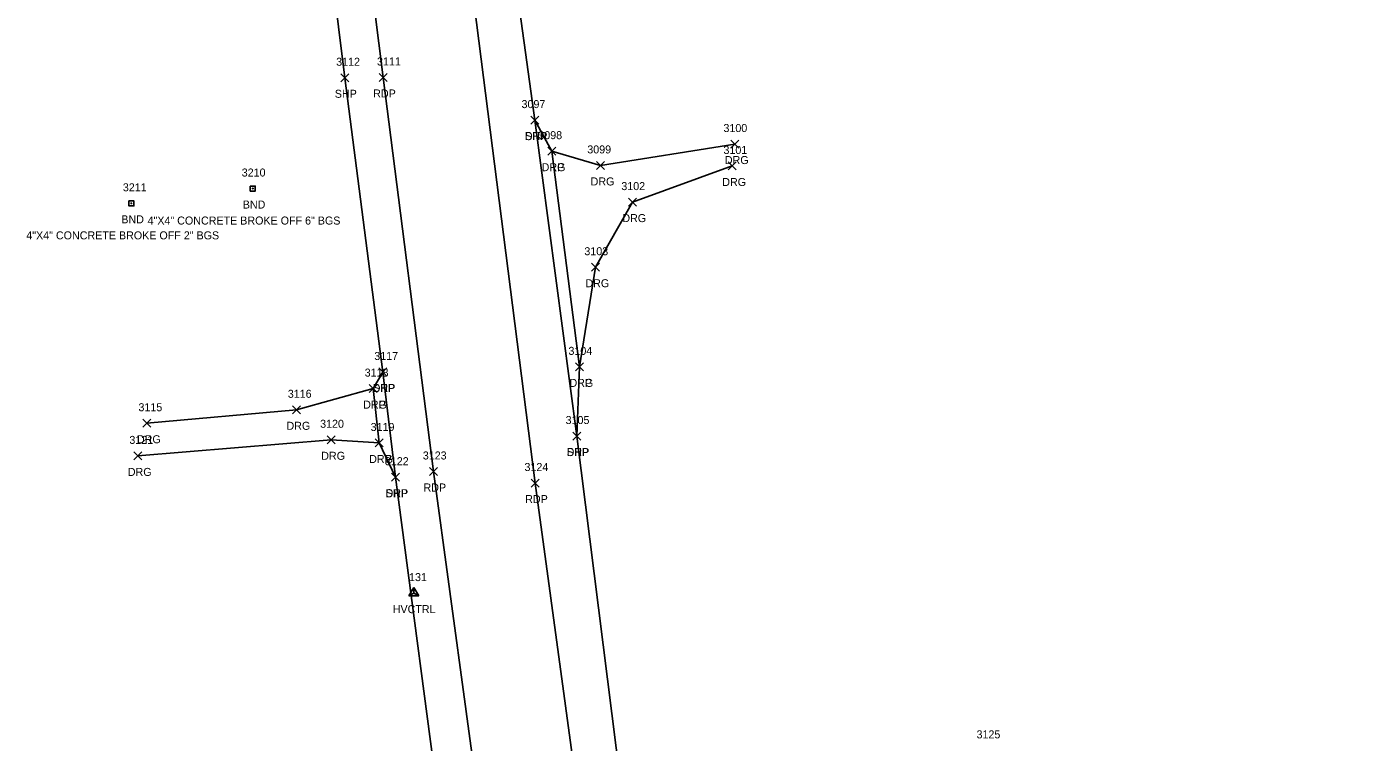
# Model space of a CAD drawing. Extents: x 1443071 to 1445292, y 614024 to 622563.
# Drawn here: x 1444204.2 to 1444535.7, y 617034.6 to 617213.4 of the extents above; entities that cross this region are included whole.
import ezdxf

# ---------------------------------------------------------------- set-up
doc = ezdxf.new("R2010")
doc.units = 0
for name, color, linetype in [('C_A', 7, 'Continuous'), ('C_I', 7, 'Continuous'), ('CPSM', 7, 'Continuous'), ('L_I', 7, 'Continuous'), ('M_A', 7, 'Continuous'), ('M_C', 7, 'Continuous'), ('M_I', 7, 'Continuous'), ('MHBP', 7, 'Continuous'), ('P_A', 7, 'Continuous'), ('P_I', 7, 'Continuous'), ('P_TIC', 7, 'Continuous'), ('PET', 7, 'Continuous'), ('PSP', 7, 'Continuous'), ('R_A', 7, 'Continuous'), ('R_I', 7, 'Continuous'), ('R_TIC', 7, 'Continuous'), ('RDG', 7, 'Continuous'), ('RDP', 7, 'Continuous')]:
    doc.layers.add(name, color=color, linetype=linetype)

msp = doc.modelspace()

# ---------------------------------------------------------------- linework, layer by layer
at = {"layer": 'CPSM'}
for p, q in [((1444299.72, 617071.16), (1444300.97, 617073.32)), ((1444299.72, 617071.16), (1444300.97, 617071.88)), ((1444299.72, 617071.16), (1444302.22, 617071.16)), ((1444302.22, 617071.16), (1444300.97, 617073.32)), ((1444300.97, 617071.88), (1444300.97, 617073.32)), ((1444300.97, 617071.88), (1444300.97, 617071.88)), ((1444300.97, 617071.88), (1444302.22, 617071.16))]:
    msp.add_line(p, q, dxfattribs=at)
at = {"layer": 'MHBP'}
for points in [[(1444260.08, 617173.56), (1444261.33, 617173.56), (1444261.33, 617172.31), (1444260.08, 617172.31)], [(1444229.73, 617169.86), (1444230.98, 617169.86), (1444230.98, 617168.61), (1444229.73, 617168.61)]]:
    msp.add_lwpolyline(points, close=True, dxfattribs=at)
for centre in [(1444260.71, 617172.94), (1444230.36, 617169.24)]:
    msp.add_circle(centre, 0.0833, dxfattribs=at)
at = {"layer": 'P_TIC'}
for points in [[(1444282.66, 617199.61), (1444284.66, 617201.61)], [(1444284.66, 617199.61), (1444282.66, 617201.61)], [(1444292.29, 617199.68), (1444294.29, 617201.68)], [(1444294.29, 617199.68), (1444292.29, 617201.68)], [(1444330.18, 617189.03), (1444332.18, 617191.03)], [(1444332.18, 617189.03), (1444330.18, 617191.03)], [(1444292.17, 617126.11), (1444294.17, 617128.11)], [(1444294.17, 617126.11), (1444292.17, 617128.11)], [(1444340.63, 617110.11), (1444342.63, 617112.11)], [(1444342.63, 617110.11), (1444340.63, 617112.11)], [(1444295.38, 617099.83), (1444297.38, 617101.83)], [(1444297.38, 617099.83), (1444295.38, 617101.83)], [(1444304.86, 617101.26), (1444306.86, 617103.26)], [(1444306.86, 617101.26), (1444304.86, 617103.26)], [(1444330.28, 617098.37), (1444332.28, 617100.37)], [(1444332.28, 617098.37), (1444330.28, 617100.37)]]:
    msp.add_lwpolyline(points, dxfattribs=at)
at = {"layer": 'PET'}
for points in [[(1444290.04, 617226.49), (1444293.29, 617200.68), (1444305.86, 617102.26), (1444318.1, 617012.36), (1444328.61, 616929.53), (1444340.48, 616832.7), (1444349.36, 616766.46), (1444359.48, 616687.73), (1444375.76, 616559.26), (1444386.72, 616474.82), (1444392.98, 616424.11), (1444399.64, 616374.74), (1444405.35, 616331.68), (1444416.25, 616246.74), (1444430.45, 616134.64), (1444440.68, 616052.2), (1444460.71, 615897.87), (1444469.48, 615825.17), (1444479.32, 615749.85), (1444490.82, 615663.43), (1444501.1, 615593.99)], [(1444314.9, 617227.6), (1444331.28, 617099.37), (1444342.74, 617014.98), (1444353.45, 616933.43), (1444365.99, 616834.42), (1444373.87, 616769.68), (1444384.25, 616690.54), (1444399.86, 616561.36), (1444411.32, 616477.78), (1444418.43, 616426.72), (1444433.04, 616320.39), (1444440.5, 616248.61), (1444455.15, 616137.88), (1444465.57, 616054.84), (1444485.3, 615900.9), (1444494.14, 615826.26), (1444503.74, 615751.94), (1444515.41, 615666.64), (1444525.64, 615597.72)]]:
    msp.add_lwpolyline(points, dxfattribs=at)
at = {"layer": 'PSP'}
for points in [[(1444325.72, 617229.34), (1444331.18, 617190.03), (1444341.63, 617111.11), (1444353.65, 617016.1), (1444364.55, 616934.22), (1444377.14, 616835.48), (1444385.64, 616770.75), (1444395.97, 616692.96), (1444412.43, 616562.03), (1444423.01, 616481.11), (1444430.88, 616420.51), (1444443.11, 616323.39), (1444448.99, 616268.44), (1444454, 616230.8), (1444465.61, 616141.36), (1444476.5, 616056.13), (1444483.28, 615998.72), (1444489.46, 615946.55), (1444495.54, 615902.14), (1444505.18, 615827.19), (1444514.81, 615753.2), (1444525.85, 615667.7), (1444535.69, 615600.77)], [(1444280.5, 617226.12), (1444283.66, 617200.61), (1444293.17, 617127.11), (1444296.38, 617100.83), (1444308.28, 617010.91), (1444318.74, 616928.98), (1444325.56, 616872.02), (1444335.05, 616795.34), (1444338.72, 616765.27), (1444349.45, 616686.56), (1444353.22, 616653.3), (1444364.91, 616559.25), (1444375.85, 616473.62), (1444383.24, 616422.24), (1444388.01, 616382.64), (1444395.12, 616329.81), (1444406.01, 616244.88), (1444420.16, 616134.13), (1444430.49, 616051.12), (1444450.17, 615896.86), (1444459.96, 615823.48), (1444469.66, 615749), (1444481.34, 615661.86), (1444491.6, 615592.34)]]:
    msp.add_lwpolyline(points, dxfattribs=at)
at = {"layer": 'R_TIC'}
for points in [[(1444330.18, 617189.03), (1444332.18, 617191.03)], [(1444332.18, 617189.03), (1444330.18, 617191.03)], [(1444334.37, 617181.27), (1444336.37, 617183.27)], [(1444336.37, 617181.27), (1444334.37, 617183.27)], [(1444334.37, 617181.27), (1444336.37, 617183.27)], [(1444336.37, 617181.27), (1444334.37, 617183.27)], [(1444380.15, 617183.05), (1444382.15, 617185.05)], [(1444382.15, 617183.05), (1444380.15, 617185.05)], [(1444346.61, 617177.71), (1444348.61, 617179.71)], [(1444348.61, 617177.71), (1444346.61, 617179.71)], [(1444379.5, 617177.57), (1444381.5, 617179.57)], [(1444381.5, 617177.57), (1444379.5, 617179.57)], [(1444354.54, 617168.55), (1444356.54, 617170.55)], [(1444356.54, 617168.55), (1444354.54, 617170.55)], [(1444345.31, 617152.28), (1444347.31, 617154.28)], [(1444347.31, 617152.28), (1444345.31, 617154.28)], [(1444292.17, 617126.11), (1444294.17, 617128.11)], [(1444294.17, 617126.11), (1444292.17, 617128.11)], [(1444341.33, 617127.39), (1444343.33, 617129.39)], [(1444343.33, 617127.39), (1444341.33, 617129.39)], [(1444341.33, 617127.39), (1444343.33, 617129.39)], [(1444343.33, 617127.39), (1444341.33, 617129.39)], [(1444289.78, 617121.96), (1444291.78, 617123.96)], [(1444291.78, 617121.96), (1444289.78, 617123.96)], [(1444289.78, 617121.96), (1444291.78, 617123.96)], [(1444291.78, 617121.96), (1444289.78, 617123.96)], [(1444270.62, 617116.67), (1444272.62, 617118.67)], [(1444272.62, 617116.67), (1444270.62, 617118.67)], [(1444233.26, 617113.31), (1444235.26, 617115.31)], [(1444235.26, 617113.31), (1444233.26, 617115.31)], [(1444279.3, 617109.18), (1444281.3, 617111.18)], [(1444281.3, 617109.18), (1444279.3, 617111.18)], [(1444291.28, 617108.38), (1444293.28, 617110.38)], [(1444293.28, 617108.38), (1444291.28, 617110.38)], [(1444291.28, 617108.38), (1444293.28, 617110.38)], [(1444293.28, 617108.38), (1444291.28, 617110.38)], [(1444340.63, 617110.11), (1444342.63, 617112.11)], [(1444342.63, 617110.11), (1444340.63, 617112.11)], [(1444230.98, 617105.15), (1444232.98, 617107.15)], [(1444232.98, 617105.15), (1444230.98, 617107.15)], [(1444295.38, 617099.83), (1444297.38, 617101.83)], [(1444297.38, 617099.83), (1444295.38, 617101.83)]]:
    msp.add_lwpolyline(points, dxfattribs=at)
at = {"layer": 'RDG'}
for points in [[(1444335.37, 617182.27), (1444347.61, 617178.71), (1444381.15, 617184.05)], [(1444380.5, 617178.57), (1444355.54, 617169.55), (1444346.31, 617153.28), (1444342.33, 617128.39)], [(1444234.26, 617114.31), (1444271.62, 617117.67), (1444290.78, 617122.96)], [(1444292.28, 617109.38), (1444280.3, 617110.18), (1444231.98, 617106.15)]]:
    msp.add_lwpolyline(points, dxfattribs=at)
at = {"layer": 'RDP'}
for points in [[(1444331.18, 617190.03), (1444335.37, 617182.27), (1444342.33, 617128.39), (1444341.63, 617111.11)], [(1444293.17, 617127.11), (1444290.78, 617122.96), (1444292.28, 617109.38), (1444296.38, 617100.83)]]:
    msp.add_lwpolyline(points, dxfattribs=at)

# ---------------------------------------------------------------- texts
at = {"layer": 'C_A'}
msp.add_text('HVCTRL', height=2, dxfattribs=at).set_placement((1444295.66, 617066.88))
at = {"layer": 'C_I'}
msp.add_text('131', height=2, dxfattribs=at).set_placement((1444299.74, 617074.88))
at = {"layer": 'L_I'}
msp.add_text('3125', height=2, dxfattribs=at).set_placement((1444441.52, 617035.59))
at = {"layer": 'M_A'}
for p in [(1444258.19, 617167.94), (1444227.85, 617164.24)]:
    msp.add_text('BND', height=2, dxfattribs=at).set_placement(p)
at = {"layer": 'M_C'}
for s, p in [('4"X4" CONCRETE BROKE OFF 6" BGS', (1444234.41, 617163.94)), ('4"X4" CONCRETE BROKE OFF 2" BGS', (1444204.11, 617160.24))]:
    msp.add_text(s, height=2, dxfattribs=at).set_placement(p)
at = {"layer": 'M_I'}
for s, p in [('3210', (1444257.93, 617175.94)), ('3211', (1444228.23, 617172.24))]:
    msp.add_text(s, height=2, dxfattribs=at).set_placement(p)
at = {"layer": 'P_A'}
for s, p in [('SHP', (1444281.19, 617195.61)), ('RDP', (1444290.78, 617195.68)), ('SHP', (1444328.72, 617185.03)), ('SHP', (1444290.71, 617122.11)), ('SHP', (1444339.16, 617106.11)), ('SHP', (1444293.92, 617095.83)), ('RDP', (1444303.35, 617097.26)), ('RDP', (1444328.76, 617094.37))]:
    msp.add_text(s, height=2, dxfattribs=at).set_placement(p)
at = {"layer": 'P_I'}
for s, p in [('3112', (1444281.53, 617203.61)), ('3111', (1444291.73, 617203.68)), ('3097', (1444327.84, 617193.03)), ('3117', (1444291.05, 617130.11)), ('3105', (1444338.85, 617114.11)), ('3123', (1444303.17, 617105.26)), ('3122', (1444293.69, 617103.83)), ('3124', (1444328.58, 617102.37))]:
    msp.add_text(s, height=2, dxfattribs=at).set_placement(p)
at = {"layer": 'R_A'}
for s, p in [('DRP', (1444328.67, 617185.03)), ('DRG', (1444378.64, 617179.05)), ('DRG', (1444332.86, 617177.27)), ('DRP', (1444332.86, 617177.27)), ('DRG', (1444345.1, 617173.71)), ('DRG', (1444377.99, 617173.57)), ('DRG', (1444353.03, 617164.55)), ('DRG', (1444343.8, 617148.28)), ('DRP', (1444290.66, 617122.11)), ('DRG', (1444339.82, 617123.39)), ('DRP', (1444339.82, 617123.39)), ('DRG', (1444288.27, 617117.96)), ('DRP', (1444288.27, 617117.96)), ('DRG', (1444269.11, 617112.67)), ('DRG', (1444231.75, 617109.31)), ('DRG', (1444277.79, 617105.18)), ('DRP', (1444339.11, 617106.11)), ('DRG', (1444289.77, 617104.38)), ('DRP', (1444289.77, 617104.38)), ('DRG', (1444229.47, 617101.15)), ('DRP', (1444293.87, 617095.83))]:
    msp.add_text(s, height=2, dxfattribs=at).set_placement(p)
at = {"layer": 'R_I'}
for s, p in [('3097', (1444327.84, 617193.03)), ('3098', (1444332.03, 617185.27)), ('3098', (1444332.03, 617185.27)), ('3100', (1444378.29, 617187.05)), ('3099', (1444344.27, 617181.71)), ('3101', (1444378.29, 617181.57)), ('3102', (1444352.77, 617172.55)), ('3103', (1444343.54, 617156.28)), ('3117', (1444291.05, 617130.11)), ('3104', (1444339.56, 617131.39)), ('3104', (1444339.56, 617131.39)), ('3118', (1444288.65, 617125.96)), ('3118', (1444288.65, 617125.96)), ('3116', (1444269.44, 617120.67)), ('3115', (1444232.13, 617117.31)), ('3120', (1444277.52, 617113.18)), ('3119', (1444290.14, 617112.38)), ('3119', (1444290.14, 617112.38)), ('3105', (1444338.85, 617114.11)), ('3121', (1444229.86, 617109.15)), ('3122', (1444293.69, 617103.83))]:
    msp.add_text(s, height=2, dxfattribs=at).set_placement(p)

doc.saveas('drawing.dxf')
